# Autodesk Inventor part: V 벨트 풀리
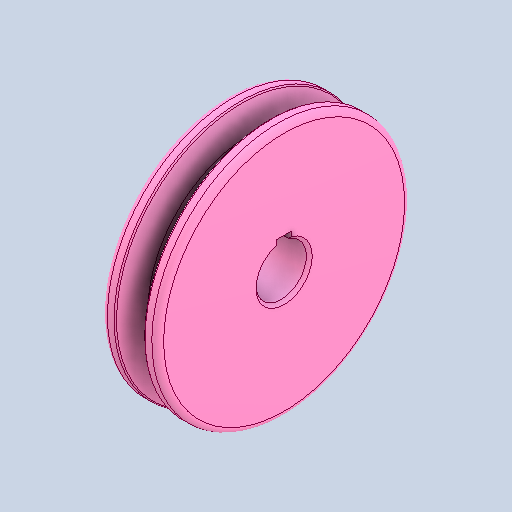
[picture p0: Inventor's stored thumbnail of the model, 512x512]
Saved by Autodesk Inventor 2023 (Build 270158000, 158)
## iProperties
Created: 2025-03
Part Number: V 벨트 풀리
Material: 알루미늄 6061
Document SubType Name: Modeling
Designer: ADMIN_PC
Density: 2.71 g/cm^3
Appearance: 기본값
Author: jhkim
Sending System: Autodesk Inventor 2025
Preprocessor: ST-DEVELOPER v20
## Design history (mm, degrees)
feature "솔리드1"
node "솔리드2"
